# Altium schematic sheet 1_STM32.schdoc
size 307 x 218 mm; Symbol: Sheet-Symbol_A4; Device: Sheet-Symbol_A4; @Project Name: Hexapod; @Page Count: 5; @Update Date: 2024-12-19; @Create Date: 2024-10-10; @Schematic Name: Schematic1; @Page No: 1; @Page Name: STM32; Company: EasyEDA.com; Version: V1.0; Page Size: A4; @Create Time: 19:36:18; @Update Time: 12:57:34; Title Block Position: 3; Width: 1170; Height: 825; Region Start: 1; X Region Count: 6; Y Region Count: 4; Blade Width: 10; @Board Name: Hexapod
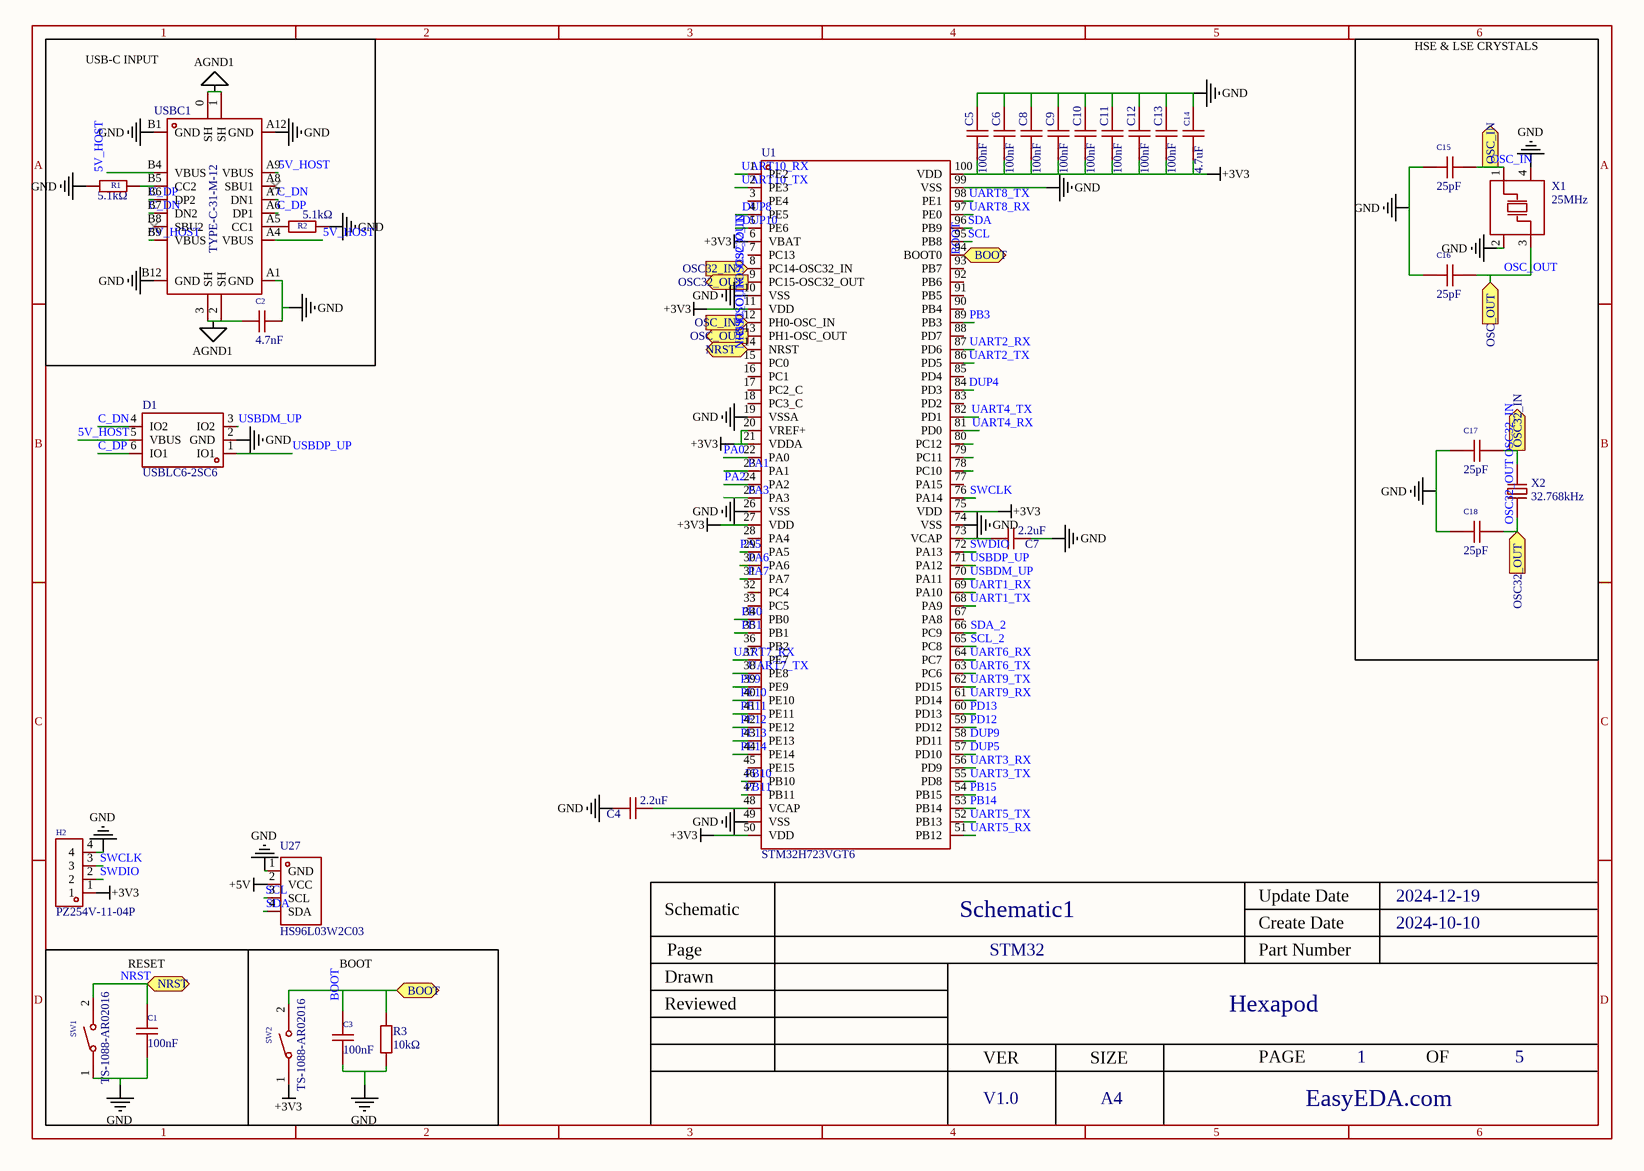
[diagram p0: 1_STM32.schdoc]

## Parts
C1  100nF  [C0402]
C2  4.7nF  [C0402]
C3  100nF  [C0402]
C4  2.2uF  [C0402]
C5  100nF  [C0402]
C6  100nF  [C0402]
C7  2.2uF  [C0402]
C8  100nF  [C0402]
C9  100nF  [C0402]
C10  100nF  [C0402]
C11  100nF  [C0402]
C12  100nF  [C0402]
C13  100nF  [C0402]
C14  4.7uF  [C0402]
C15  25pF  [C0402]
C16  25pF  [C0402]
C17  25pF  [C0402]
C18  25pF  [C0402]
D1  USBLC6-2SC6  [SOT-23-6_L2.9-W1.6-P0.95-LS2.8-BL]
H2  PZ254V-11-04P  [HDR-TH_4P-P2.54-V-M]
R1  5.1kΩ  [R0402]
R2  5.1kΩ  [R0402]
R3  10kΩ  [R0402]
SW1  TS-1088-AR02016  [SW-SMD_L3.9-W3.0-P4.45]
SW2  TS-1088-AR02016  [SW-SMD_L3.9-W3.0-P4.45]
U1  STM32H723VGT6  [LQFP-100_L14.0-W14.0-P0.50-LS16.0-BL]
U27  HS96L03W2C03  [OLED-TH_L27.8-W27.2-P2.54_C9900033791]
USBC1  TYPE-C-31-M-12  [USB-C_SMD-TYPE-C-31-M-12]
X1  25MHz  [CRYSTAL-SMD_4P-L3.2-W2.5-BL]
X2  32.768kHz  [OSC-SMD_L3.2-W1.5]

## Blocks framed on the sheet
USB-C INPUT: C2 R1 R2 USBC1
HSE & LSE CRYSTALS: C15-C18 X1 X2
RESET: C1 SW1
BOOT: C3 R3 SW2

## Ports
BOOT (bidir), NRST (bidir), OSC32_IN (in), OSC32_IN (out), OSC32_OUT (in), OSC32_OUT (out), OSC_IN (in), OSC_IN (out), OSC_OUT (in), OSC_OUT (out)

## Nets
+3V3: C5.1 C6.1 C8.1 C9.1 C10.1 C11.1 C12.1 C13.1 C14.1 H2.1 SW2.1 U1.6(VBAT) U1.11(VDD) U1.20(VREF+) U1.21(VDDA) U1.27(VDD) U1.50(VDD) U1.75(VDD) U1.100(VDD)
+5V: U27.2(VCC)
AGND1: C2.1 USBC1.0(SH) USBC1.1(SH) USBC1.2(SH) USBC1.3(SH)
GND: C1.1 C2.2 C3.1 C4.1 C5.2 C6.2 C7.2 C8.2 C9.2 C10.2 C11.2 C12.2 C13.2 C14.2 C15.1 C16.1 C17.1 C18.1 D1.2(GND) H2.4 R1.1 R2.2 R3.1 SW1.1 U1.10(VSS) U1.19(VSSA) U1.26(VSS) U1.49(VSS) U1.74(VSS) U1.99(VSS) U27.1(GND) USBC1.A1(GND) USBC1.A12(GND) USBC1.B1(GND) USBC1.B12(GND) X1.2(GND) X1.4(GND)
5V_HOST: D1.5(VBUS) USBC1.A4(VBUS) USBC1.A9(VBUS) USBC1.B4(VBUS) USBC1.B9(VBUS)
BOOT: C3.2 R3.2 SW2.2 U1.94(BOOT0) ; port BOOT
C_DN: D1.4(IO2) USBC1.A7(DN1) USBC1.B7(DN2)
C_DP: D1.6(IO1) USBC1.A6(DP1) USBC1.B6(DP2)
DUP4: U1.84(PD3)
DUP5: U1.57(PD10)
DUP8: U1.4(PE5)
DUP9: U1.58(PD11)
DUP10: U1.5(PE6)
NRST: C1.2 SW1.2 U1.14(NRST) ; port NRST
OSC32_IN: C17.2 U1.8(PC14-OSC32_IN) X2.2 ; port OSC32_IN
OSC32_OUT: C18.2 U1.9(PC15-OSC32_OUT) X2.1 ; port OSC32_OUT
OSC_IN: C15.2 U1.12(PH0-OSC_IN) X1.1(OSC1) ; port OSC_IN
OSC_OUT: C16.2 U1.13(PH1-OSC_OUT) X1.3(OSC2) ; port OSC_OUT
PA0: U1.22(PA0)
PA1: U1.23(PA1)
PA2: U1.24(PA2)
PA3: U1.25(PA3)
PA5: U1.29(PA5)
PA6: U1.30(PA6)
PA7: U1.31(PA7)
PB0: U1.34(PB0)
PB1: U1.35(PB1)
PB3: U1.89(PB3)
PB10: U1.46(PB10)
PB11: U1.47(PB11)
PB14: U1.53(PB14)
PB15: U1.54(PB15)
PD12: U1.59(PD12)
PD13: U1.60(PD13)
PE9: U1.39(PE9)
PE10: U1.40(PE10)
PE11: U1.41(PE11)
PE12: U1.42(PE12)
PE13: U1.43(PE13)
PE14: U1.44(PE14)
SCL: U1.95(PB8) U27.3(SCL)
SCL_2: U1.65(PC8)
SDA: U1.96(PB9) U27.4(SDA)
SDA_2: U1.66(PC9)
SWCLK: H2.3 U1.76(PA14)
SWDIO: H2.2 U1.72(PA13)
UART1_RX: U1.69(PA10)
UART1_TX: U1.68(PA9)
UART2_RX: U1.87(PD6)
UART2_TX: U1.86(PD5)
UART3_RX: U1.56(PD9)
UART3_TX: U1.55(PD8)
UART4_RX: U1.81(PD0)
UART4_TX: U1.82(PD1)
UART5_RX: U1.51(PB12)
UART5_TX: U1.52(PB13)
UART6_RX: U1.64(PC7)
UART6_TX: U1.63(PC6)
UART7_RX: U1.37(PE7)
UART7_TX: U1.38(PE8)
UART8_RX: U1.97(PE0)
UART8_TX: U1.98(PE1)
UART9_RX: U1.61(PD14)
UART9_TX: U1.62(PD15)
UART10_RX: U1.1(PE2)
UART10_TX: U1.2(PE3)
USBDM_UP: D1.3(IO2) U1.70(PA11)
USBDP_UP: D1.1(IO1) U1.71(PA12)
NetC4_2: C4.2 U1.48(VCAP)
NetC7_1: C7.1 U1.73(VCAP)
NetR1_2: R1.2 USBC1.B5(CC2)
NetR2_1: R2.1 USBC1.A5(CC1)

Not connected (* = marked no-connect by the designer): U1 3(PE4) 7(PC13) 15(PC0) 16(PC1) 17(PC2_C) 18(PC3_C) 28(PA4) 32(PC4) 33(PC5) 36(PB2) 45(PE15) 67(PA8) 77(PA15) 78(PC10) 79(PC11) 80(PC12) 83(PD2) 85(PD4) 88(PD7) 90(PB4) 91(PB5) 92(PB6) 93(PB7); USBC1 A8(SBU1)* B8(SBU2)*

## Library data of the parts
C1 C3 = CT41G-0402-2X1-16V-0.1μF-K(N): Manufacturer: TORCH(火炬); Add into BOM: yes; Tolerance: ±10%
C2 = CC0402KRX7R9BB472: Manufacturer: YAGEO(国巨); Add into BOM: yes; Tolerance: ±10%
C4 C7 = GRM155R61A225KE95D: Manufacturer: muRata(村田); Add into BOM: yes; Tolerance: ±10%
C5 C6 C8-C13 = GRM155R71A104KA01D: Manufacturer: muRata(村田); Add into BOM: yes; Tolerance: ±10%
C14 = CL05A475KP5NRNC: Manufacturer: SAMSUNG(三星); Add into BOM: yes; Tolerance: ±10%
C15-C18 = TCC0402COG250K500AT: Manufacturer: CCTC(三环); Add into BOM: yes; Tolerance: ±10%
D1 = USBLC6-2SC6_C2827654: Manufacturer: TECH PUBLIC(台舟); Add into BOM: yes; polarity: Unidirectional; Reverse Stand-Off Voltage (Vrwm): 5V; Maximum Clamping Voltage: 12V; Peak Pulse Current (Ipp): 6A; Peak Pulse Power Dissipation (Ppp): 150W; Breakdown Voltage: 6V; Reverse Leakage Current (Ir): 80nA; Number of Lines: Dual channel; level of protection: IEC 61000-4-2; Type: ESD
H2 = PZ254V-11-04P: Manufacturer: XFCN(兴飞); Symbol: PZ254V-11-04P_C2691448; Add into BOM: yes; Pin Structure: 1x4P; Pitch: 2.54mm; Circluar Pins/Square Pins: Square Pins; Current Rating (Max): 3A; Voltage Rating (Max): 250V
R1 R2 = RMC04025.1K1%N: Manufacturer: Tyohm(幸亚电阻); Add into BOM: yes; Tolerance: ±1%
R3 = RC0402FR-0710KL: Manufacturer: YAGEO(国巨); Add into BOM: yes; Tolerance: ±1%; Temperature Coefficient: ±100ppm/℃
SW1 SW2 = TS-1088-AR02016: Manufacturer: XUNPU(讯普); Add into BOM: yes; Circuit: SPST; Actuator Style: Round Button; Operating Force: 160gf; Switch Length: 4mm; Switch Width: 3mm; Switch Height: 2mm; Strike Gundam: 不带; Contact Current: 50mA; Voltage Rating (DC): 12V; Insulation Resistance: 100MΩ; Actuator/Cap Color: Black; Pin Style: SMDSplicing; Mechanical Life: 10万次
U1 = STM32H723VGT6: Manufacturer: ST(意法半导体); Add into BOM: yes; Program Storage Size: 1MB; RAM Size: 564KB; GPIO Ports Number: 80; Operating Voltage Range: 1.71V~3.6V; CPU Maximum Speed: 550MHz; Program Memory Type: FLASH; ADC (Bit): 16bit; DAC (Bit): 12bit; Peripheral/Function: DMA；LCD/LED Driver
U27 = HS96L03W2C03: Manufacturer: HS(汉昇); Add into BOM: yes; Main Control Chip: SSD1315; Interface Type: I2C; Pixel Resolution: 128x64
USBC1 = TYPE-C-31-M-12: Manufacturer: 韩国韩荣; Add into BOM: yes; Connector Type: Type-C; Gender: Female; Number of Contacts: 16P; Number of Ports: 1; Current Rating - Power (Max): 5A
X1 = X322525MOB4SI: Manufacturer: YXC(扬兴晶振); Add into BOM: yes; Crystal Type: Surface Mount Crystal; Normal temperature Frequency Tolerance: ±10ppm; Frequency Stability(Full temperature range): ±20ppm
X2 = X321532768KGD2SI: Manufacturer: YXC(扬兴晶振); Add into BOM: yes; Crystal Type: Surface Mount Crystal; Normal temperature Frequency Tolerance: ±20ppm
